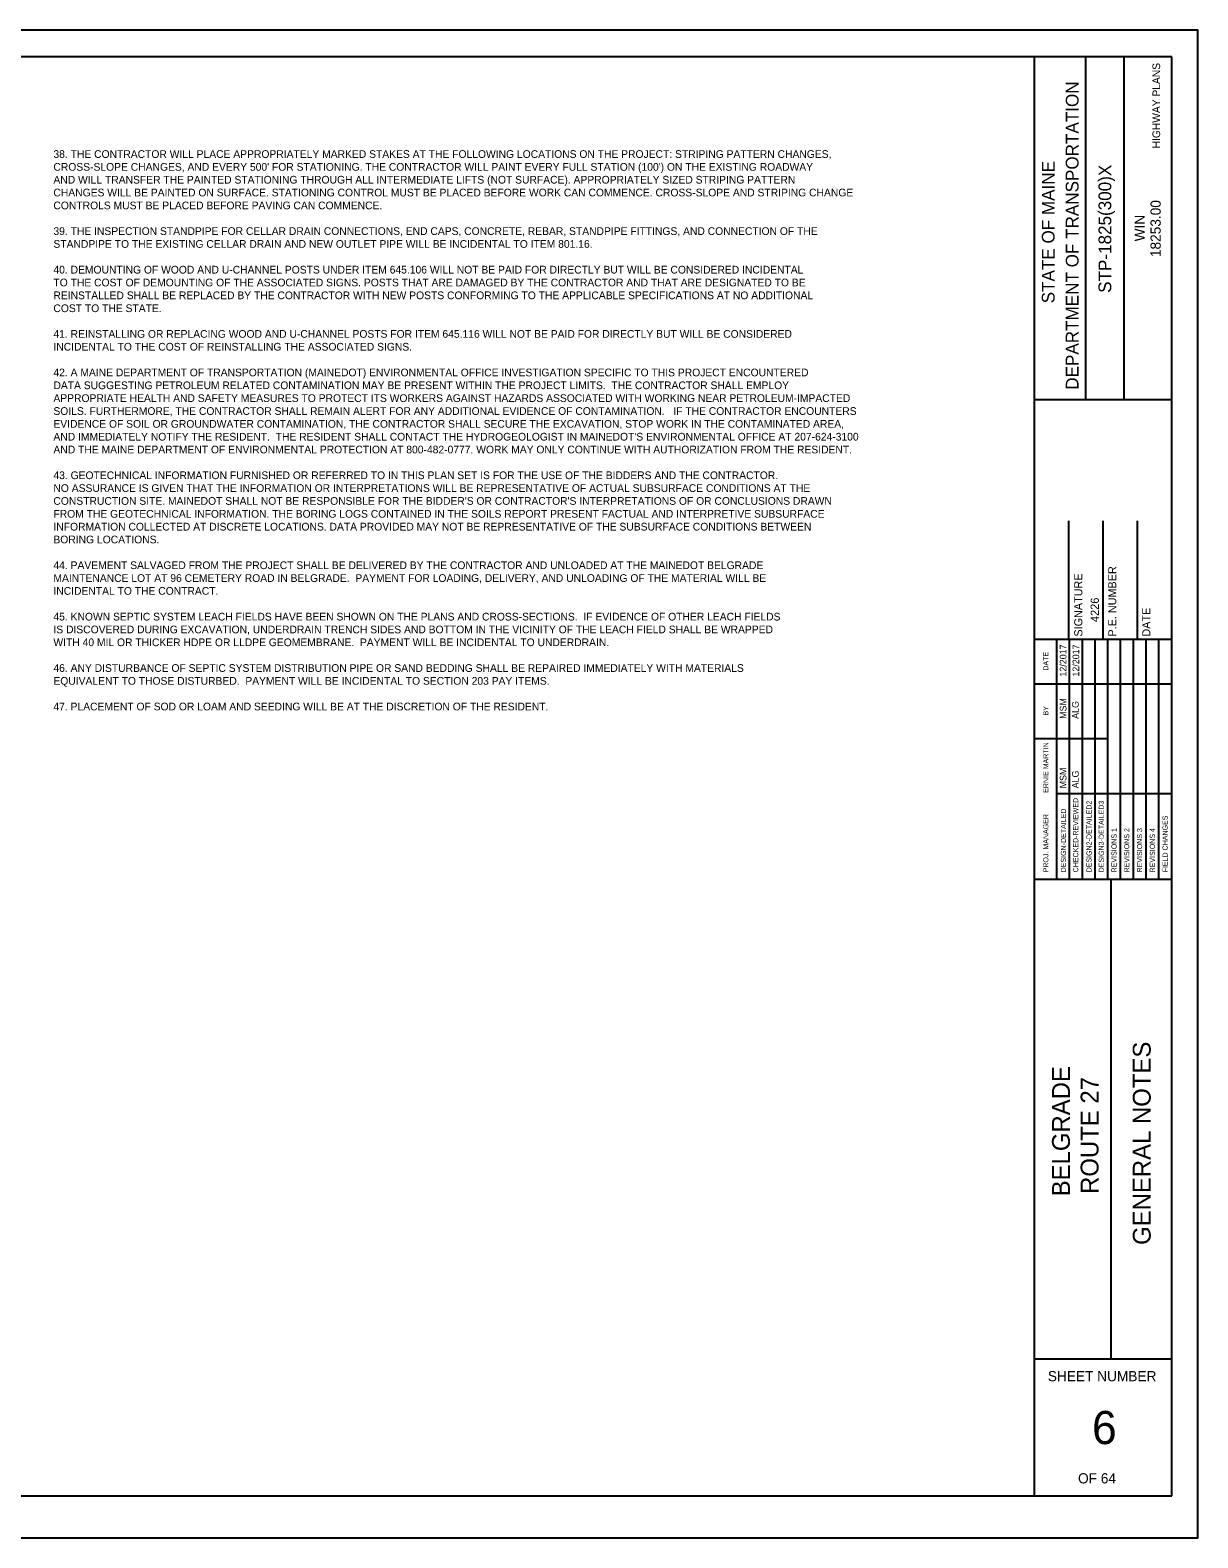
# Model space of a CAD drawing. Extents: x -0.13 to 5.88, y -0.37 to 1.78.
# Drawn here: x 1.279 to 2.698, y -0.051 to 1.782 of the extents above; entities that cross this region are included whole.
import ezdxf

# ---------------------------------------------------------------- set-up
doc = ezdxf.new("R2010")
doc.units = 0
for name, color, linetype in [('ANNOTATION', 7, 'Continuous'), ('BORDER', 7, 'Continuous'), ('PLOT BOUNDARY', 7, 'Continuous')]:
    doc.layers.add(name, color=color, linetype=linetype)

msp = doc.modelspace()

# ---------------------------------------------------------------- linework, layer by layer
at = {"layer": 'BORDER'}
for p, q in [((2.6667, 1.75), (0, 1.75)), ((2.5, 0), (2.5, 1.75)), ((2.5621, 1.3333), (2.5621, 1.75)), ((2.6087, 1.3333), (2.6087, 1.75)), ((2.6667, 0), (2.6667, 1.75)), ((2.5, 1.3332), (2.6667, 1.3332)), ((2.5417, 1.0417), (2.5417, 1.1858)), ((2.5833, 1.0417), (2.5833, 1.1858)), ((2.625, 1.0417), (2.625, 1.1858)), ((2.5, 1.0417), (2.6667, 1.0417)), ((2.5, 0.75), (2.6667, 0.75)), ((2.5932, 0.1667), (2.5932, 0.75)), ((2.5, 0.1667), (2.6667, 0.1667)), ((0, 0), (2.6667, 0))]:
    msp.add_line(p, q, dxfattribs=at)
for points in [[(2.5269, 0.9875), (2.5269, 1.0417)], [(2.5269, 0.7501), (2.5269, 1.0299)], [(2.5425, 0.7501), (2.5425, 1.0417)], [(2.558, 1.0417), (2.558, 0.7501)], [(2.5735, 0.7501), (2.5735, 1.0417)], [(2.589, 0.7501), (2.589, 1.0417)], [(2.6046, 0.7501), (2.6046, 1.0417)], [(2.6201, 0.7501), (2.6201, 1.0417)], [(2.6356, 0.7501), (2.6356, 1.0417)], [(2.6512, 0.7501), (2.6512, 1.0417)], [(2.5, 0.9875), (2.6667, 0.9875)], [(2.5, 0.9209), (2.5269, 0.9209)], [(2.5269, 0.9209), (2.589, 0.9209)], [(2.5269, 0.8542), (2.6667, 0.8542)]]:
    msp.add_lwpolyline(points, dxfattribs=at)
at = {"layer": 'PLOT BOUNDARY'}
msp.add_lwpolyline([(-0.1349, -0.051), (2.6984, -0.051), (2.6984, 1.7823), (-0.1349, 1.7823)], close=True, dxfattribs=at)

# ---------------------------------------------------------------- texts
at = {"layer": 'ANNOTATION'}
for s, p in [('38. THE CONTRACTOR WILL PLACE APPROPRIATELY MARKED STAKES AT THE FOLLOWING LOCATIONS ON THE PROJECT: STRIPING PATTERN CHANGES,', (1.307, 1.627)), ("CROSS-SLOPE CHANGES, AND EVERY 500' FOR STATIONING. THE CONTRACTOR WILL PAINT EVERY FULL STATION (100') ON THE EXISTING ROADWAY ", (1.307, 1.6114)), ('AND WILL TRANSFER THE PAINTED STATIONING THROUGH ALL INTERMEDIATE LIFTS (NOT SURFACE). APPROPRIATELY SIZED STRIPING PATTERN', (1.307, 1.5958)), ('CHANGES WILL BE PAINTED ON SURFACE. STATIONING CONTROL MUST BE PLACED BEFORE WORK CAN COMMENCE. CROSS-SLOPE AND STRIPING CHANGE ', (1.307, 1.5802)), ('CONTROLS MUST BE PLACED BEFORE PAVING CAN COMMENCE.', (1.307, 1.5645)), ('39. THE INSPECTION STANDPIPE FOR CELLAR DRAIN CONNECTIONS, END CAPS, CONCRETE, REBAR, STANDPIPE FITTINGS, AND CONNECTION OF THE', (1.307, 1.5333)), ('STANDPIPE TO THE EXISTING CELLAR DRAIN AND NEW OUTLET PIPE WILL BE INCIDENTAL TO ITEM 801.16.', (1.307, 1.5177)), ('40. DEMOUNTING OF WOOD AND U-CHANNEL POSTS UNDER ITEM 645.106 WILL NOT BE PAID FOR DIRECTLY BUT WILL BE CONSIDERED INCIDENTAL', (1.307, 1.4864)), ('TO THE COST OF DEMOUNTING OF THE ASSOCIATED SIGNS. POSTS THAT ARE DAMAGED BY THE CONTRACTOR AND THAT ARE DESIGNATED TO BE ', (1.307, 1.4708)), ('COST TO THE STATE.', (1.307, 1.4395)), ('REINSTALLED SHALL BE REPLACED BY THE CONTRACTOR WITH NEW POSTS CONFORMING TO THE APPLICABLE SPECIFICATIONS AT NO ADDITIONAL', (1.307, 1.4552)), ('41. REINSTALLING OR REPLACING WOOD AND U-CHANNEL POSTS FOR ITEM 645.116 WILL NOT BE PAID FOR DIRECTLY BUT WILL BE CONSIDERED', (1.307, 1.4083)), ('INCIDENTAL TO THE COST OF REINSTALLING THE ASSOCIATED SIGNS.', (1.307, 1.3927)), ('42. A MAINE DEPARTMENT OF TRANSPORTATION (MAINEDOT) ENVIRONMENTAL OFFICE INVESTIGATION SPECIFIC TO THIS PROJECT ENCOUNTERED', (1.307, 1.3614)), ('APPROPRIATE HEALTH AND SAFETY MEASURES TO PROTECT ITS WORKERS AGAINST HAZARDS ASSOCIATED WITH WORKING NEAR PETROLEUM-IMPACTED', (1.307, 1.3302)), ('DATA SUGGESTING PETROLEUM RELATED CONTAMINATION MAY BE PRESENT WITHIN THE PROJECT LIMITS.  THE CONTRACTOR SHALL EMPLOY', (1.307, 1.3458)), ('SOILS. FURTHERMORE, THE CONTRACTOR SHALL REMAIN ALERT FOR ANY ADDITIONAL EVIDENCE OF CONTAMINATION.   IF THE CONTRACTOR ENCOUNTERS', (1.307, 1.3145)), ('EVIDENCE OF SOIL OR GROUNDWATER CONTAMINATION, THE CONTRACTOR SHALL SECURE THE EXCAVATION, STOP WORK IN THE CONTAMINATED AREA,', (1.307, 1.2989)), ("AND IMMEDIATELY NOTIFY THE RESIDENT.  THE RESIDENT SHALL CONTACT THE HYDROGEOLOGIST IN MAINEDOT'S ENVIRONMENTAL OFFICE AT 207-624-3100 ", (1.307, 1.2833)), ('AND THE MAINE DEPARTMENT OF ENVIRONMENTAL PROTECTION AT 800-482-0777. WORK MAY ONLY CONTINUE WITH AUTHORIZATION FROM THE RESIDENT.', (1.307, 1.2677)), ('43. GEOTECHNICAL INFORMATION FURNISHED OR REFERRED TO IN THIS PLAN SET IS FOR THE USE OF THE BIDDERS AND THE CONTRACTOR.', (1.307, 1.2364)), ('NO ASSURANCE IS GIVEN THAT THE INFORMATION OR INTERPRETATIONS WILL BE REPRESENTATIVE OF ACTUAL SUBSURFACE CONDITIONS AT THE ', (1.307, 1.2208)), ("CONSTRUCTION SITE. MAINEDOT SHALL NOT BE RESPONSIBLE FOR THE BIDDER'S OR CONTRACTOR'S INTERPRETATIONS OF OR CONCLUSIONS DRAWN", (1.307, 1.2052)), ('FROM THE GEOTECHNICAL INFORMATION. THE BORING LOGS CONTAINED IN THE SOILS REPORT PRESENT FACTUAL AND INTERPRETIVE SUBSURFACE ', (1.307, 1.1895)), ('INFORMATION COLLECTED AT DISCRETE LOCATIONS. DATA PROVIDED MAY NOT BE REPRESENTATIVE OF THE SUBSURFACE CONDITIONS BETWEEN', (1.307, 1.1739)), ('BORING LOCATIONS.', (1.307, 1.1583)), ('44. PAVEMENT SALVAGED FROM THE PROJECT SHALL BE DELIVERED BY THE CONTRACTOR AND UNLOADED AT THE MAINEDOT BELGRADE', (1.307, 1.127)), ('MAINTENANCE LOT AT 96 CEMETERY ROAD IN BELGRADE.  PAYMENT FOR LOADING, DELIVERY, AND UNLOADING OF THE MATERIAL WILL BE ', (1.307, 1.1114)), ('INCIDENTAL TO THE CONTRACT.', (1.307, 1.0958)), ('45. KNOWN SEPTIC SYSTEM LEACH FIELDS HAVE BEEN SHOWN ON THE PLANS AND CROSS-SECTIONS.  IF EVIDENCE OF OTHER LEACH FIELDS', (1.307, 1.0645)), ('IS DISCOVERED DURING EXCAVATION, UNDERDRAIN TRENCH SIDES AND BOTTOM IN THE VICINITY OF THE LEACH FIELD SHALL BE WRAPPED', (1.307, 1.0489)), ('WITH 40 MIL OR THICKER HDPE OR LLDPE GEOMEMBRANE.  PAYMENT WILL BE INCIDENTAL TO UNDERDRAIN.', (1.307, 1.0333)), ('46. ANY DISTURBANCE OF SEPTIC SYSTEM DISTRIBUTION PIPE OR SAND BEDDING SHALL BE REPAIRED IMMEDIATELY WITH MATERIALS', (1.307, 1.002)), ('EQUIVALENT TO THOSE DISTURBED.  PAYMENT WILL BE INCIDENTAL TO SECTION 203 PAY ITEMS.', (1.307, 0.9864)), ('47. PLACEMENT OF SOD OR LOAM AND SEEDING WILL BE AT THE DISCRETION OF THE RESIDENT.', (1.307, 0.9552))]:
    msp.add_text(s, height=0.009375, dxfattribs=at).set_placement(p)
msp.add_text('4226', height=0.01, rotation=90, dxfattribs=at).set_placement((2.5781, 1.0626))
at = {"layer": 'BORDER'}
for s, height, p in [('HIGHWAY PLANS', 0.009317, (2.6526, 1.6386)), ('DEPARTMENT OF TRANSPORTATION', 0.015529, (2.5534, 1.3451)), ('STATE OF MAINE', 0.015529, (2.5243, 1.4502)), ('STP-1825(300)X', 0.015529, (2.5932, 1.4629)), ('18253.00', 0.01242, (2.6533, 1.5064)), ('WIN', 0.01242, (2.6339, 1.5255)), ('SIGNATURE', 0.00984, (2.558, 1.0449)), ('P.E. NUMBER', 0.009843, (2.5993, 1.0449)), ('DATE', 0.00984, (2.6407, 1.0449)), ('12/2017', 0.00808, (2.5387, 0.9963)), ('12/2017', 0.00808, (2.5542, 0.9963)), ('DATE', 0.00619, (2.5167, 1.0035)), ('BY', 0.00619, (2.5167, 0.949)), ('MSM', 0.00808, (2.5387, 0.9449)), ('ALG', 0.00808, (2.5536, 0.9449)), ('ERNIE MARTIN', 0.006212, (2.5167, 0.8549)), ('MSM', 0.00808, (2.5387, 0.8604)), ('ALG', 0.00808, (2.5536, 0.8604)), ('CHECKED-REVIEWED', 0.006212, (2.553, 0.7582)), ('PROJ. MANAGER', 0.006212, (2.5167, 0.7582)), ('DESIGN-DETAILED', 0.006212, (2.5381, 0.7582)), ('DESIGN2-DETAILED2', 0.006212, (2.5692, 0.7582)), ('DESIGN3-DETAILED3', 0.006212, (2.5841, 0.7582)), ('REVISIONS 1', 0.006212, (2.5996, 0.7582)), ('REVISIONS 2', 0.006212, (2.6151, 0.7582)), ('REVISIONS 3', 0.006212, (2.6307, 0.7582)), ('REVISIONS 4', 0.006212, (2.6462, 0.7582)), ('FIELD CHANGES', 0.006212, (2.6617, 0.7582)), ('GENERAL NOTES', 0.021738, (2.6411, 0.3052)), ('BELGRADE', 0.02174, (2.5429, 0.3643)), ('ROUTE 27', 0.02174, (2.5777, 0.3672))]:
    msp.add_text(s, height=height, rotation=90, dxfattribs=at).set_placement(p)
for s, height, p in [('SHEET NUMBER', 0.012421, (2.5161, 0.1394)), ('6', 0.0403, (2.5698, 0.063)), ('OF 64', 0.01242, (2.5528, 0.0152))]:
    msp.add_text(s, height=height, dxfattribs=at).set_placement(p)

doc.saveas('drawing.dxf')
